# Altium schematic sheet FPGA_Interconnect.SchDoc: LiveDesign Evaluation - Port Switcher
size A4; Organization: Altium Limited; Address1: L3, 12a Rodborough Rd; Address2: Frenchs Forest; Address3: NSW; Address4: Australia 2086
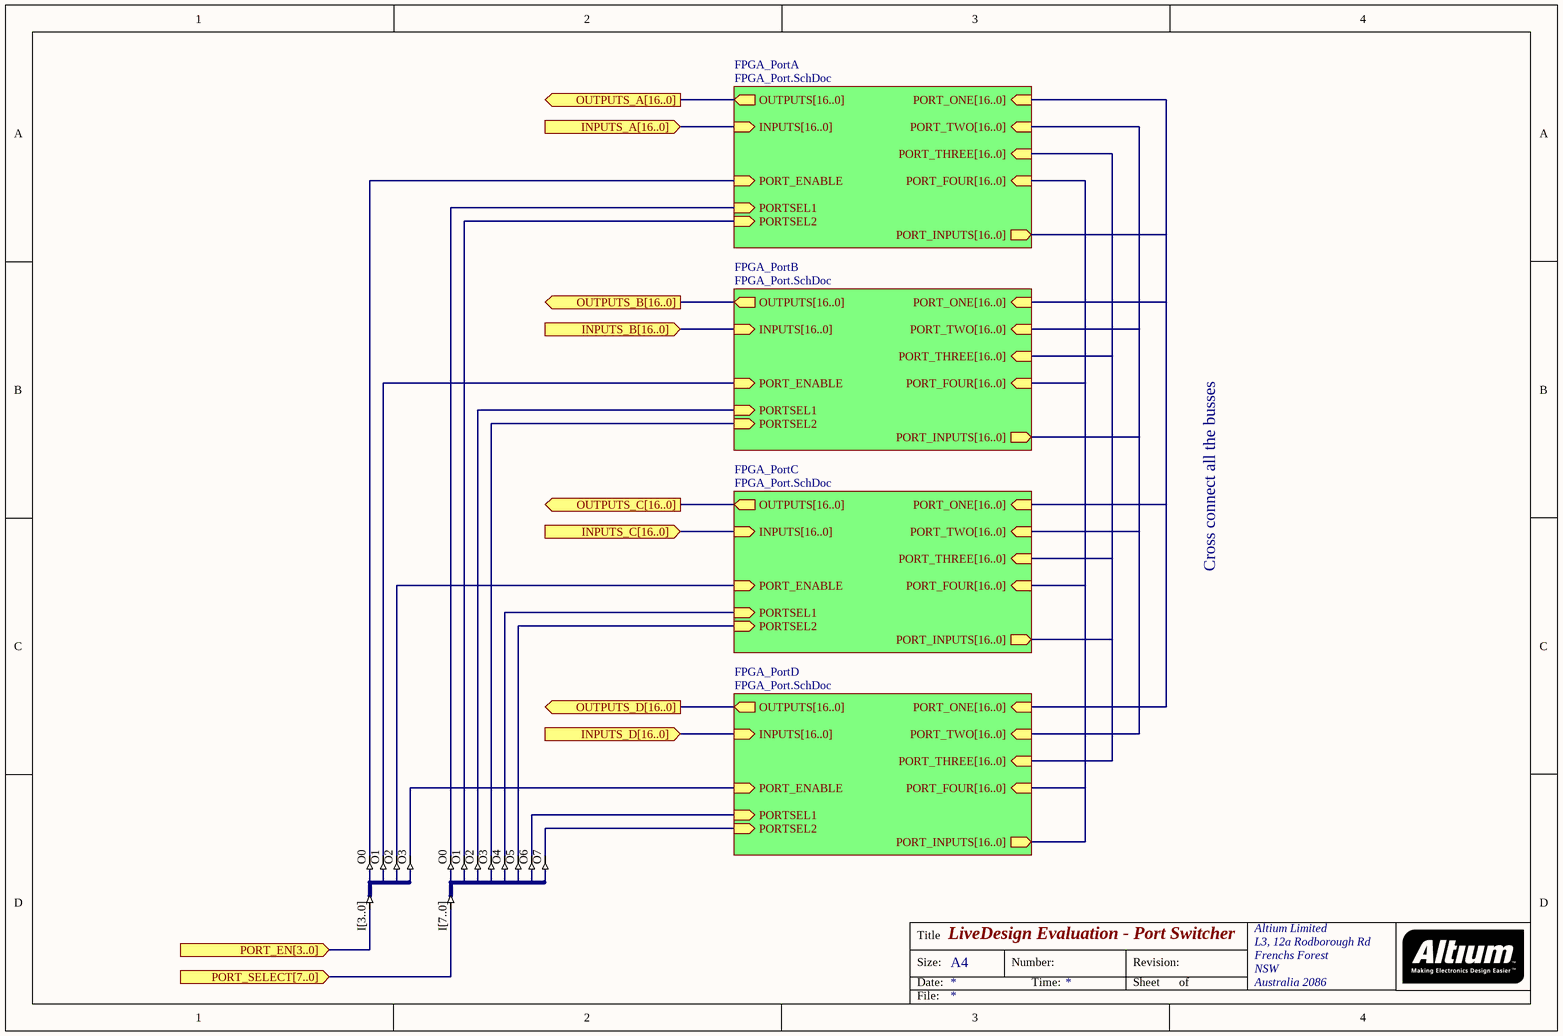
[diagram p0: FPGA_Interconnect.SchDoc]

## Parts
U1  J4B_4S  (value not drawn)
U2  J8B_8S  (value not drawn)

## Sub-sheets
FPGA_PortA = FPGA_Port.SchDoc: PORT_ONE[16..0] (in), PORTSEL1 (in), PORT_TWO[16..0] (in), PORT_THREE[16..0] (in), PORT_FOUR[16..0] (in), PORT_ENABLE (in), OUTPUTS[16..0] (out), PORTSEL2 (in), INPUTS[16..0] (in), PORT_INPUTS[16..0] (out)
FPGA_PortB = FPGA_Port.SchDoc: PORT_ONE[16..0] (in), PORTSEL1 (in), PORT_TWO[16..0] (in), PORT_THREE[16..0] (in), PORT_FOUR[16..0] (in), PORT_ENABLE (in), OUTPUTS[16..0] (out), PORTSEL2 (in), INPUTS[16..0] (in), PORT_INPUTS[16..0] (out)
FPGA_PortC = FPGA_Port.SchDoc: PORT_ONE[16..0] (in), PORTSEL1 (in), PORT_TWO[16..0] (in), PORT_THREE[16..0] (in), PORT_FOUR[16..0] (in), PORT_ENABLE (in), OUTPUTS[16..0] (out), PORTSEL2 (in), INPUTS[16..0] (in), PORT_INPUTS[16..0] (out)
FPGA_PortD = FPGA_Port.SchDoc: PORT_ONE[16..0] (in), PORTSEL1 (in), PORT_TWO[16..0] (in), PORT_THREE[16..0] (in), PORT_FOUR[16..0] (in), PORT_ENABLE (in), OUTPUTS[16..0] (out), PORTSEL2 (in), INPUTS[16..0] (in), PORT_INPUTS[16..0] (out)

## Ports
INPUTS_A[16..0] (in), INPUTS_B[16..0] (in), INPUTS_C[16..0] (in), INPUTS_D[16..0] (in), OUTPUTS_A[16..0] (out), OUTPUTS_B[16..0] (out), OUTPUTS_C[16..0] (out), OUTPUTS_D[16..0] (out), PORT_EN[3..0] (in), PORT_SELECT[7..0] (in)

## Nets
NetU1_O0: U1.O0 ; sheet FPGA_PortA/PORT_ENABLE
NetU1_O1: U1.O1 ; sheet FPGA_PortB/PORT_ENABLE
NetU1_O2: U1.O2 ; sheet FPGA_PortC/PORT_ENABLE
NetU1_O3: U1.O3 ; sheet FPGA_PortD/PORT_ENABLE
NetU2_O0: U2.O0 ; sheet FPGA_PortA/PORTSEL1
NetU2_O1: U2.O1 ; sheet FPGA_PortA/PORTSEL2
NetU2_O2: U2.O2 ; sheet FPGA_PortB/PORTSEL1
NetU2_O3: U2.O3 ; sheet FPGA_PortB/PORTSEL2
NetU2_O4: U2.O4 ; sheet FPGA_PortC/PORTSEL1
NetU2_O5: U2.O5 ; sheet FPGA_PortC/PORTSEL2
NetU2_O6: U2.O6 ; sheet FPGA_PortD/PORTSEL1
NetU2_O7: U2.O7 ; sheet FPGA_PortD/PORTSEL2

Not connected (* = marked no-connect by the designer): U1 I[3..0]; U2 I[7..0]

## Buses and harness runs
bus port INPUTS_A[16..0] = sheet FPGA_PortA/INPUTS[16..0]
bus port INPUTS_B[16..0] = sheet FPGA_PortB/INPUTS[16..0]
bus port INPUTS_C[16..0] = sheet FPGA_PortC/INPUTS[16..0]
bus port INPUTS_D[16..0] = sheet FPGA_PortD/INPUTS[16..0]
bus port OUTPUTS_A[16..0] = sheet FPGA_PortA/OUTPUTS[16..0]
bus port OUTPUTS_B[16..0] = sheet FPGA_PortB/OUTPUTS[16..0]
bus port OUTPUTS_C[16..0] = sheet FPGA_PortC/OUTPUTS[16..0]
bus port OUTPUTS_D[16..0] = sheet FPGA_PortD/OUTPUTS[16..0]
bus sheet FPGA_PortA/PORT_FOUR[16..0] = sheet FPGA_PortB/PORT_FOUR[16..0] = sheet FPGA_PortC/PORT_FOUR[16..0] = sheet FPGA_PortD/PORT_FOUR[16..0] = sheet FPGA_PortD/PORT_INPUTS[16..0]
bus sheet FPGA_PortA/PORT_INPUTS[16..0] = sheet FPGA_PortA/PORT_ONE[16..0] = sheet FPGA_PortB/PORT_ONE[16..0] = sheet FPGA_PortC/PORT_ONE[16..0] = sheet FPGA_PortD/PORT_ONE[16..0]
bus sheet FPGA_PortA/PORT_THREE[16..0] = sheet FPGA_PortB/PORT_THREE[16..0] = sheet FPGA_PortC/PORT_INPUTS[16..0] = sheet FPGA_PortC/PORT_THREE[16..0] = sheet FPGA_PortD/PORT_THREE[16..0]
bus sheet FPGA_PortA/PORT_TWO[16..0] = sheet FPGA_PortB/PORT_INPUTS[16..0] = sheet FPGA_PortB/PORT_TWO[16..0] = sheet FPGA_PortC/PORT_TWO[16..0] = sheet FPGA_PortD/PORT_TWO[16..0]

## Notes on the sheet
- Cross connect all the busses

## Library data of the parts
U1 = J4B_4S: 4-Bit input bus to 4 Single pin outputs; ArchiveName: GENERIC; VHDLIB_SIM: GENERIC_LIB
U2 = J8B_8S: 8-Bit input bus to 8 single pin outputs; ArchiveName: GENERIC; VHDLIB_SIM: GENERIC_LIB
